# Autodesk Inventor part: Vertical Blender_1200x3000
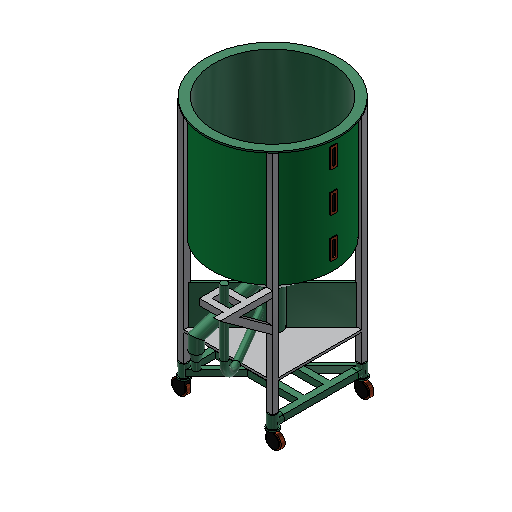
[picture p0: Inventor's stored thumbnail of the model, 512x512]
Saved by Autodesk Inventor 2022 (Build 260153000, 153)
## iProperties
RuleStatus: InUse
Created: 2013-08
Part Number: Vertical Blender_1200x3000
Material: 一般
Document SubType Name: Modeling
Density: 1 g/cm^3
Appearance: 既定
Key Parameters: Diameter=1200.000 mm;Height=3000.000 mm;
Author: Autodesk, Inc.
Title: Vertical Blender
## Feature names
1. Extrusion1
2. Extrusion2
3. Extrusion3
4. Extrusion4
5. Extrusion5
6. Extrusion7
7. Mirror1
8. Mirror2
9. Extrusion10
10. Extrusion11
11. Extrusion12
12. Mirror3
13. Mirror4
14. Extrusion13
15. Extrusion14
16. Loft2
17. Extrusion15
18. Extrusion16
19. Extrusion17
20. Circular Pattern1
21. Sweep1
22. Loft3
23. Extrusion18
24. Loft4
25. Extrusion19
26. Extrusion20
27. Extrusion21
28. Extrusion22
29. Extrusion23
30. Extrusion24
31. Sweep2
32. Extrusion25
## Parameters: d5 = 0, d9 = 0, d15 = 0, d22 = 0, d23 = 115 mm, d32 = 115 mm, d33 = 115 mm, d34 = 115 mm, d36 = 0, d47 = 0, d48 = 115 mm, d53 = 0, d54 = 0, d66 = 0, d75 = 0, d78 = 0, d82 = 0, d84 = 0, d92 = 0, d93 = 90 deg, d94 = 0, d95 = 90 deg, d97 = 0, d98 = 15 mm, d99 = 0, d101 = 0, d104 = 360 deg, d110 = 0, d111 = 55 deg, d116 = 0, d117 = 90 deg, d118 = 0, d119 = 90 deg, d121 = 0, d125 = 0, d126 = 90 deg, d127 = 0, d128 = 90 deg, d130 = 0, d131 = 375 mm, d147 = 0, d148 = 0, d151 = 45 mm, d152 = 45 mm, d161 = 0, d166 = 0, d172 = 0, d180 = 0, d194 = 0, d199 = 0, d200 = 0, d201 = 0
